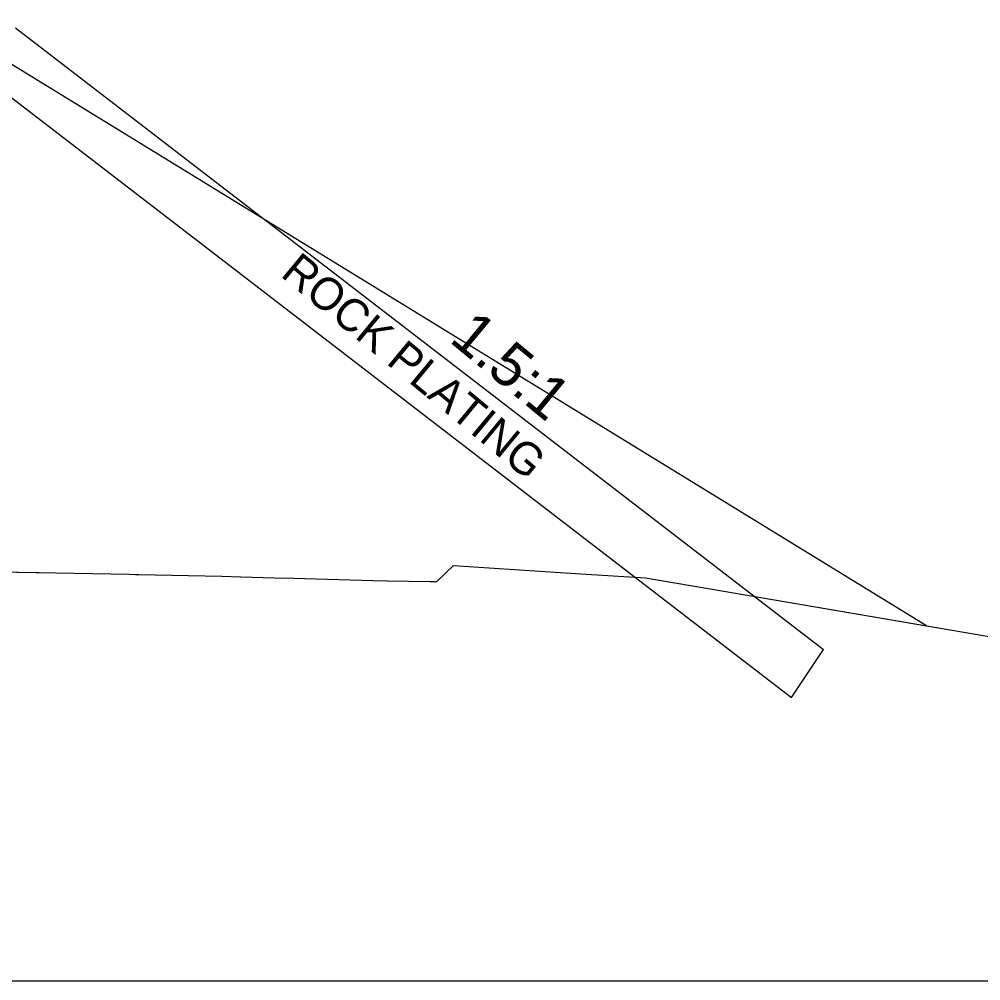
# Model space of a CAD drawing. Extents: x -26 to 1640245, y -10 to 842531.
# Drawn here: x 180.95 to 214.32, y 0 to 33.37 of the extents above; entities that cross this region are included whole.
import ezdxf

# ---------------------------------------------------------------- set-up
doc = ezdxf.new("R2010")
doc.units = 0
for name, color, linetype in [('Exist Cross Section Cell', 7, 'Continuous'), ('Exist XS Ground Line', 7, 'Continuous'), ('Prop CMT Slope Grass', 7, 'Continuous'), ('Prop XS Class B Stone Ditch Liner', 7, 'Continuous'), ('Prop XS Side Slope Text', 7, 'Continuous'), ('Scratch_Level_3', 7, 'Continuous')]:
    doc.layers.add(name, color=color, linetype=linetype)

msp = doc.modelspace()

# ---------------------------------------------------------------- linework, layer by layer
at = {"layer": 'Exist Cross Section Cell'}
msp.add_line((150, 0), (300, 0), dxfattribs=at)
at = {"layer": 'Exist XS Ground Line'}
for p, q in [((195.745, 14.143), (196.02, 14.409)), ((196.02, 14.409), (200.254, 14.136)), ((179.658, 14.202), (181.533, 14.172)), ((181.533, 14.172), (181.644, 14.174)), ((181.644, 14.174), (182.226, 14.163)), ((182.226, 14.163), (184.764, 14.109)), ((184.764, 14.109), (184.981, 14.105)), ((184.981, 14.105), (185.104, 14.103)), ((185.104, 14.103), (186.813, 14.071)), ((186.813, 14.071), (187.983, 14.041)), ((187.983, 14.041), (188.646, 14.021)), ((188.646, 14.021), (189.806, 13.989)), ((195.446, 13.853), (195.745, 14.143)), ((200.254, 14.136), (202.683, 13.987)), ((189.806, 13.989), (190.478, 13.97)), ((190.478, 13.97), (190.862, 13.959)), ((190.862, 13.959), (193.221, 13.893)), ((193.221, 13.893), (193.726, 13.88)), ((193.726, 13.88), (195.204, 13.857)), ((195.204, 13.857), (195.446, 13.853)), ((202.683, 13.987), (205.339, 13.529)), ((205.339, 13.529), (221.519, 10.77))]:
    msp.add_line(p, q, dxfattribs=at)
at = {"layer": 'Prop CMT Slope Grass'}
msp.add_line((177.147, 33.373), (207.748, 9.834), dxfattribs=at)
at = {"layer": 'Prop XS Class B Stone Ditch Liner'}
for p in [(180.822, 33.069), (207.748, 9.834)]:
    msp.add_line(p, (208.86, 11.502), dxfattribs=at)
at = {"layer": 'Scratch_Level_3'}
msp.add_line((212.439, 12.318), (180.374, 32.001), dxfattribs=at)
msp.add_lwpolyline([(179.658, 14.202), (181.533, 14.172), (181.644, 14.174), (182.226, 14.163), (184.764, 14.109), (184.981, 14.105), (185.104, 14.103), (186.813, 14.071), (187.983, 14.041), (188.646, 14.021), (189.806, 13.989), (190.478, 13.97), (190.862, 13.959), (193.221, 13.893), (193.726, 13.88), (195.204, 13.857), (195.446, 13.853), (195.745, 14.143), (196.02, 14.409), (200.254, 14.136), (202.683, 13.987), (205.339, 13.529), (212.439, 12.318)], dxfattribs=at)

# ---------------------------------------------------------------- texts
at = {"layer": 'Prop XS Side Slope Text'}
for s, height, p in [('ROCK PLATING', 1.125, (189.982, 24.474)), ('1.5:1', 1.5, (195.836, 22.205))]:
    msp.add_text(s, height=height, rotation=320.4211, dxfattribs=at).set_placement(p)

doc.saveas('drawing.dxf')
